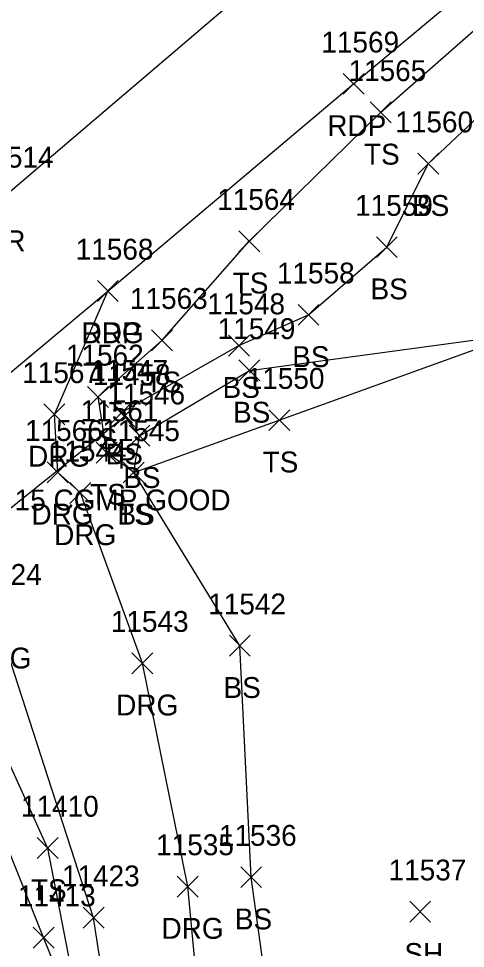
# Model space of a CAD drawing. Extents: x 1475671 to 1477951, y 592661 to 593821.
# Drawn here: x 1476935.7 to 1476978.4, y 593335.9 to 593424.9 of the extents above; entities that cross this region are included whole.
import ezdxf

# ---------------------------------------------------------------- set-up
doc = ezdxf.new("R2010")
doc.units = 0
for name, color, linetype in [('D_A', 7, 'Continuous'), ('D_C', 7, 'Continuous'), ('D_I', 7, 'Continuous'), ('D_TIC', 7, 'Continuous'), ('DCP', 7, 'Continuous'), ('L_A', 7, 'Continuous'), ('L_I', 7, 'Continuous'), ('L_TIC', 7, 'Continuous'), ('LELB', 7, 'Continuous'), ('P_A', 7, 'Continuous'), ('P_I', 7, 'Continuous'), ('P_TIC', 7, 'Continuous'), ('PET', 7, 'Continuous'), ('PRC', 7, 'Continuous'), ('R_A', 7, 'Continuous'), ('R_I', 7, 'Continuous'), ('R_TIC', 7, 'Continuous'), ('RDG', 7, 'Continuous')]:
    doc.layers.add(name, color=color, linetype=linetype)

msp = doc.modelspace()

# ---------------------------------------------------------------- linework, layer by layer
at = {"layer": 'D_TIC'}
for points in [[(1476944.815, 593385.869), (1476946.815, 593387.869)], [(1476946.815, 593385.869), (1476944.815, 593387.869)]]:
    msp.add_lwpolyline(points, dxfattribs=at)
at = {"layer": 'DCP'}
msp.add_lwpolyline([(1476922.075, 593367.764), (1476945.815, 593386.869)], dxfattribs=at)
at = {"layer": 'L_TIC'}
for points in [[(1476969.319, 593414.97), (1476971.319, 593416.97)], [(1476971.319, 593414.97), (1476969.319, 593416.97)], [(1476973.882, 593410.059), (1476975.882, 593412.059)], [(1476975.882, 593410.059), (1476973.882, 593412.059)], [(1476956.762, 593402.637), (1476958.762, 593404.637)], [(1476958.762, 593402.637), (1476956.762, 593404.637)], [(1476969.912, 593402.072), (1476971.912, 593404.072)], [(1476971.912, 593402.072), (1476969.912, 593404.072)], [(1476962.425, 593395.591), (1476964.425, 593397.591)], [(1476964.425, 593395.591), (1476962.425, 593397.591)], [(1476948.42, 593393.158), (1476950.42, 593395.158)], [(1476950.42, 593393.158), (1476948.42, 593395.158)], [(1476955.765, 593392.643), (1476957.765, 593394.643)], [(1476957.765, 593392.643), (1476955.765, 593394.643)], [(1476956.765, 593390.27), (1476958.765, 593392.27)], [(1476958.765, 593390.27), (1476956.765, 593392.27)], [(1476942.294, 593387.731), (1476944.294, 593389.731)], [(1476944.294, 593387.731), (1476942.294, 593389.731)], [(1476944.575, 593386.268), (1476946.575, 593388.268)], [(1476946.575, 593386.268), (1476944.575, 593388.268)], [(1476959.625, 593385.507), (1476961.625, 593387.507)], [(1476961.625, 593385.507), (1476959.625, 593387.507)], [(1476946.263, 593384.015), (1476948.263, 593386.015)], [(1476948.263, 593384.015), (1476946.263, 593386.015)], [(1476946.263, 593384.015), (1476948.263, 593386.015)], [(1476948.263, 593384.015), (1476946.263, 593386.015)], [(1476943.129, 593382.406), (1476945.129, 593384.406)], [(1476945.129, 593382.406), (1476943.129, 593384.406)], [(1476945.712, 593380.501), (1476947.712, 593382.501)], [(1476947.712, 593380.501), (1476945.712, 593382.501)], [(1476945.712, 593380.501), (1476947.712, 593382.501)], [(1476947.712, 593380.501), (1476945.712, 593382.501)], [(1476945.712, 593380.501), (1476947.712, 593382.501)], [(1476947.712, 593380.501), (1476945.712, 593382.501)], [(1476955.854, 593363.915), (1476957.854, 593365.915)], [(1476957.854, 593363.915), (1476955.854, 593365.915)], [(1476937.467, 593344.55), (1476939.467, 593346.55)], [(1476939.467, 593344.55), (1476937.467, 593346.55)], [(1476956.936, 593341.761), (1476958.936, 593343.761)], [(1476958.936, 593341.761), (1476956.936, 593343.761)], [(1476973.105, 593338.45), (1476975.105, 593340.45)], [(1476975.105, 593338.45), (1476973.105, 593340.45)], [(1476937.092, 593335.974), (1476939.092, 593337.974)], [(1476939.092, 593335.974), (1476937.092, 593337.974)]]:
    msp.add_lwpolyline(points, dxfattribs=at)
at = {"layer": 'LELB'}
for points in [[(1476962.153, 593268.547), (1476966.091, 593293.733), (1476962.043, 593313.07), (1476957.936, 593342.761), (1476956.854, 593364.915), (1476946.712, 593381.501), (1476947.263, 593385.015), (1476945.575, 593387.268), (1476956.765, 593393.643), (1476963.425, 593396.591), (1476970.912, 593403.072), (1476974.882, 593411.059), (1477002.6, 593437.215), (1477013.994, 593445.852), (1477022.63, 593453.147), (1477030.463, 593458.556)], [(1476946.712, 593381.501), (1476944.129, 593383.406), (1476943.294, 593388.731), (1476949.42, 593394.158), (1476957.762, 593403.637), (1476970.319, 593415.97), (1476999.654, 593441.774)], [(1476947.263, 593385.015), (1476957.765, 593391.27), (1476983.413, 593394.727), (1477004.532, 593398.403), (1477034.988, 593386.152), (1477055.579, 593372.954)], [(1476946.712, 593381.501), (1476960.625, 593386.507), (1476983.413, 593394.727), (1477006.608, 593391.876), (1477032.723, 593377.716), (1477055.579, 593372.954)], [(1476864.596, 593261.544), (1476874.406, 593280.956), (1476883.326, 593306.159), (1476889.408, 593320.173), (1476901.294, 593345.545), (1476912.706, 593361.103), (1476913.877, 593366.507), (1476917.831, 593370.133), (1476924.184, 593369.902), (1476931.137, 593361.698), (1476938.467, 593345.55), (1476942.006, 593327.254), (1476944.942, 593325.577)], [(1476942.006, 593327.254), (1476938.092, 593336.974), (1476930.657, 593355.511)]]:
    msp.add_lwpolyline(points, dxfattribs=at)
at = {"layer": 'P_TIC'}
for points in [[(1476966.732, 593417.704), (1476968.732, 593419.704)], [(1476968.732, 593417.704), (1476966.732, 593419.704)], [(1476943.228, 593397.872), (1476945.228, 593399.872)], [(1476945.228, 593397.872), (1476943.228, 593399.872)]]:
    msp.add_lwpolyline(points, dxfattribs=at)
at = {"layer": 'PET'}
msp.add_lwpolyline([(1476493.608, 593061.898), (1476518.902, 593073.258), (1476550.122, 593088.216), (1476579.1, 593105.347), (1476612.568, 593127.792), (1476627.642, 593138.007), (1476653.647, 593155.862), (1476677.366, 593174.623), (1476705.428, 593196.668), (1476722.658, 593210.687), (1476749.608, 593233.446), (1476768.814, 593249.961), (1476797.5, 593274.025), (1476824.823, 593297.545), (1476844.998, 593315.289), (1476868.192, 593333.861), (1476888.665, 593352.984), (1476918.008, 593376.949), (1476944.228, 593398.872), (1476967.732, 593418.704), (1476998.53, 593444.473)], dxfattribs=at)
at = {"layer": 'PRC'}
msp.add_lwpolyline([(1476461.982, 593064.616), (1476520.699, 593090.525), (1476540.789, 593101.338), (1476577.672, 593121.61), (1476614.511, 593145.687), (1476649.358, 593170.811), (1476687.024, 593200.014), (1476716.688, 593224.246), (1476733.583, 593238.31), (1476760.901, 593261.207), (1476795.35, 593290.137), (1476823.06, 593313.512), (1476854.069, 593339.52), (1476875.702, 593357.51), (1476907.008, 593384.083), (1476934.059, 593407.682), (1476963.455, 593432.806)], dxfattribs=at)
at = {"layer": 'R_TIC'}
for points in [[(1476943.228, 593397.872), (1476945.228, 593399.872)], [(1476945.228, 593397.872), (1476943.228, 593399.872)], [(1476938.116, 593386.059), (1476940.116, 593388.059)], [(1476940.116, 593386.059), (1476938.116, 593388.059)], [(1476938.437, 593380.513), (1476940.437, 593382.513)], [(1476940.437, 593380.513), (1476938.437, 593382.513)], [(1476940.61, 593378.547), (1476942.61, 593380.547)], [(1476942.61, 593378.547), (1476940.61, 593380.547)], [(1476946.543, 593362.242), (1476948.543, 593364.242)], [(1476948.543, 593362.242), (1476946.543, 593364.242)], [(1476950.874, 593340.862), (1476952.874, 593342.862)], [(1476952.874, 593340.862), (1476950.874, 593342.862)], [(1476941.867, 593337.882), (1476943.867, 593339.882)], [(1476943.867, 593337.882), (1476941.867, 593339.882)]]:
    msp.add_lwpolyline(points, dxfattribs=at)
at = {"layer": 'RDG'}
for points in [[(1476954.024, 593202.335), (1476939.155, 593211.898), (1476944.343, 593259.238), (1476951.524, 593281.234), (1476953.964, 593319.898), (1476951.874, 593341.862), (1476947.543, 593363.242), (1476941.61, 593379.547), (1476939.437, 593381.513), (1476939.116, 593387.059), (1476944.228, 593398.872)], [(1476850.389, 593217.62), (1476855.621, 593209.869), (1476871.373, 593205.698), (1476882.629, 593203.646), (1476898.321, 593201.519), (1476908.104, 593203.868), (1476921.634, 593214.391), (1476929.61, 593231.447), (1476934.181, 593252.228), (1476938.782, 593270.03), (1476944.381, 593296.102), (1476944.942, 593325.577), (1476942.867, 593338.882), (1476933.497, 593367.738), (1476927.304, 593373.855), (1476918.008, 593376.949)]]:
    msp.add_lwpolyline(points, dxfattribs=at)

# ---------------------------------------------------------------- texts
at = {"layer": 'D_A'}
msp.add_text('P', height=2, dxfattribs=at).set_placement((1476945.193, 593381.869))
at = {"layer": 'D_C'}
msp.add_text('15 CGMP GOOD', height=2, dxfattribs=at).set_placement((1476935.319, 593377.869))
at = {"layer": 'D_I'}
msp.add_text('11458', height=2, dxfattribs=at).set_placement((1476942.792, 593389.869))
at = {"layer": 'L_A'}
for s, p in [('TS', (1476968.728, 593410.97)), ('BS', (1476973.323, 593406.059)), ('TS', (1476956.172, 593398.637)), ('BS', (1476969.353, 593398.072)), ('BS', (1476961.866, 593391.591)), ('TS', (1476947.829, 593389.158)), ('BS', (1476955.206, 593388.643)), ('BS', (1476956.206, 593386.27)), ('TS', (1476941.703, 593383.731)), ('BS', (1476944.016, 593382.268)), ('TS', (1476959.035, 593381.507)), ('BS', (1476945.704, 593380.015)), ('BS', (1476945.704, 593380.015)), ('TS', (1476942.539, 593378.406)), ('TS', (1476945.121, 593376.501)), ('TS', (1476945.121, 593376.501)), ('BS', (1476945.153, 593376.501)), ('BS', (1476955.295, 593359.915)), ('TS', (1476936.876, 593340.55)), ('BS', (1476956.377, 593337.761)), ('SH', (1476972.593, 593334.45))]:
    msp.add_text(s, height=2, dxfattribs=at).set_placement(p)
at = {"layer": 'L_I'}
for s, p in [('11565', (1476967.248, 593418.97)), ('11560', (1476971.725, 593414.059)), ('11564', (1476954.691, 593406.637)), ('11559', (1476967.88, 593406.072)), ('11558', (1476960.402, 593399.591)), ('11563', (1476946.349, 593397.158)), ('11548', (1476953.742, 593396.643)), ('11549', (1476954.733, 593394.27)), ('11562', (1476940.223, 593391.731)), ('11547', (1476942.551, 593390.268)), ('11550', (1476957.515, 593389.507)), ('11546', (1476944.184, 593388.015)), ('11546', (1476944.184, 593388.015)), ('11561', (1476941.625, 593386.406)), ('11545', (1476943.688, 593384.501)), ('11545', (1476943.688, 593384.501)), ('11545', (1476943.688, 593384.501)), ('11542', (1476953.83, 593367.915)), ('11410', (1476935.923, 593348.55)), ('11536', (1476954.857, 593345.761)), ('11537', (1476971.081, 593342.45)), ('11413', (1476935.635, 593339.974))]:
    msp.add_text(s, height=2, dxfattribs=at).set_placement(p)
at = {"layer": 'P_A'}
for s, p in [('RDP', (1476965.22, 593413.704)), ('CR', (1476932.492, 593402.682)), ('RDP', (1476941.716, 593393.872))]:
    msp.add_text(s, height=2, dxfattribs=at).set_placement(p)
at = {"layer": 'P_I'}
for s, p in [('11569', (1476964.653, 593421.704)), ('11514', (1476931.603, 593410.682)), ('11568', (1476941.157, 593401.872))]:
    msp.add_text(s, height=2, dxfattribs=at).set_placement(p)
at = {"layer": 'R_A'}
for p in [(1476941.716, 593393.872), (1476936.604, 593382.059), (1476936.925, 593376.513), (1476939.098, 593374.547), (1476930.985, 593362.738), (1476945.031, 593358.242), (1476949.363, 593336.862)]:
    msp.add_text('DRG', height=2, dxfattribs=at).set_placement(p)
at = {"layer": 'R_I'}
for s, p in [('11568', (1476941.157, 593401.872)), ('11567', (1476936.045, 593390.059)), ('11566', (1476936.311, 593384.513)), ('11544', (1476938.586, 593382.547)), ('11424', (1476930.473, 593370.738)), ('11543', (1476944.519, 593366.242)), ('11535', (1476948.851, 593344.862)), ('11423', (1476939.843, 593341.882))]:
    msp.add_text(s, height=2, dxfattribs=at).set_placement(p)

doc.saveas('drawing.dxf')
